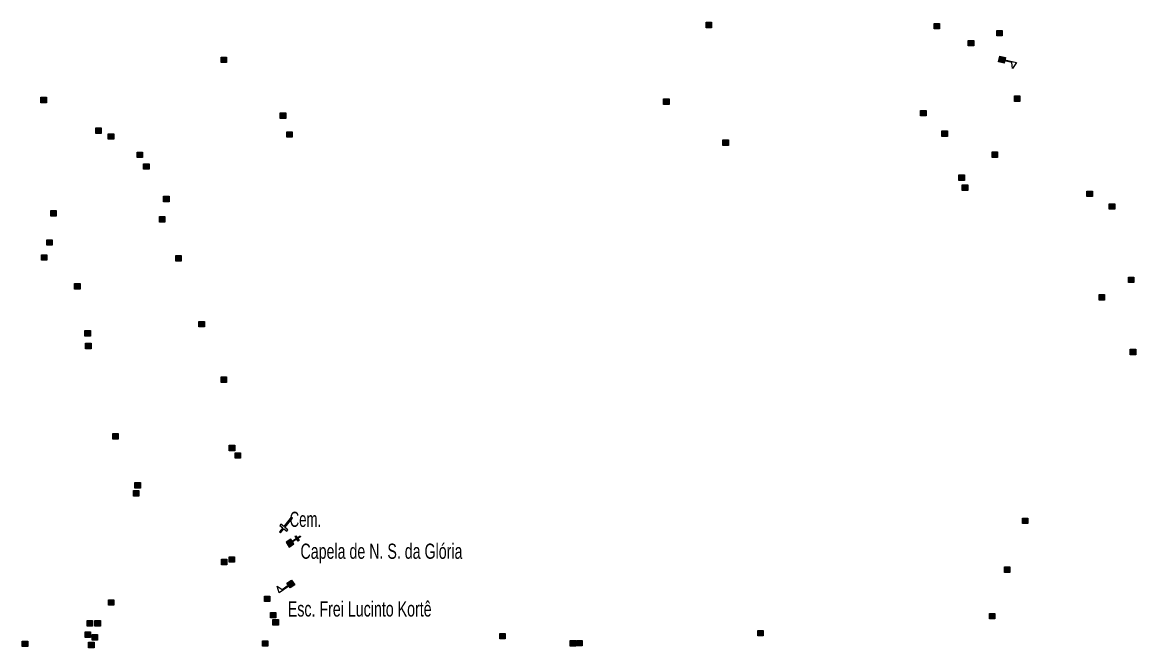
# Model space of a CAD drawing. Extents: x 649.2 to 674.4, y 7040 to 7068.1.
# Drawn here: x 649.46 to 655.33, y 7043.71 to 7047.01 of the extents above; entities that cross this region are included whole.
import ezdxf

# ---------------------------------------------------------------- set-up
doc = ezdxf.new("R2010")
doc.units = 0
doc.header["$LTSCALE"] = 0.032
for name, color, linetype, lineweight in [('2', 7, 'Continuous', 25), ('20', 7, 'Continuous', 25), ('4', 7, 'Continuous', 25), ('6', 7, 'Continuous', 25)]:
    doc.layers.add(name, color=color, linetype=linetype, lineweight=lineweight)
doc.layers.add('61', color=7, linetype='Continuous')

msp = doc.modelspace()

# ---------------------------------------------------------------- hatches: boundary and pattern name
at = {"layer": '2'}
for points in [[(653.064, 7047.0061), (653.093, 7047.0061), (653.093, 7046.9771), (653.064, 7046.9771)], [(654.2654, 7047), (654.2944, 7047), (654.2944, 7046.971), (654.2654, 7046.971)], [(654.5959, 7046.9633), (654.6249, 7046.9633), (654.6249, 7046.9343), (654.5959, 7046.9343)], [(654.4455, 7046.9105), (654.4745, 7046.9105), (654.4745, 7046.8815), (654.4455, 7046.8815)], [(650.5091, 7046.8224), (650.5381, 7046.8224), (650.5381, 7046.7934), (650.5091, 7046.7934)], [(649.5605, 7046.6114), (649.5895, 7046.6114), (649.5895, 7046.5824), (649.5605, 7046.5824)], [(652.8409, 7046.6023), (652.8699, 7046.6023), (652.8699, 7046.5733), (652.8409, 7046.5733)], [(654.6889, 7046.6178), (654.7179, 7046.6178), (654.7179, 7046.5888), (654.6889, 7046.5888)], [(650.821, 7046.5288), (650.85, 7046.5288), (650.85, 7046.4998), (650.821, 7046.4998)], [(654.1948, 7046.5417), (654.2238, 7046.5417), (654.2238, 7046.5127), (654.1948, 7046.5127)], [(649.8492, 7046.4494), (649.8782, 7046.4494), (649.8782, 7046.4204), (649.8492, 7046.4204)], [(649.915, 7046.419), (649.944, 7046.419), (649.944, 7046.39), (649.915, 7046.39)], [(650.8554, 7046.4291), (650.8844, 7046.4291), (650.8844, 7046.4001), (650.8554, 7046.4001)], [(654.3066, 7046.4341), (654.3356, 7046.4341), (654.3356, 7046.4051), (654.3066, 7046.4051)], [(653.1535, 7046.3868), (653.1825, 7046.3868), (653.1825, 7046.3578), (653.1535, 7046.3578)], [(650.0672, 7046.3227), (650.0962, 7046.3227), (650.0962, 7046.2937), (650.0672, 7046.2937)], [(654.5714, 7046.3233), (654.6004, 7046.3233), (654.6004, 7046.2943), (654.5714, 7046.2943)], [(650.1013, 7046.2606), (650.1303, 7046.2606), (650.1303, 7046.2316), (650.1013, 7046.2316)], [(654.3963, 7046.202), (654.4253, 7046.202), (654.4253, 7046.173), (654.3963, 7046.173)], [(654.4142, 7046.1493), (654.4432, 7046.1493), (654.4432, 7046.1203), (654.4142, 7046.1203)], [(655.0705, 7046.1168), (655.0995, 7046.1168), (655.0995, 7046.0878), (655.0705, 7046.0878)], [(650.2061, 7046.0901), (650.2351, 7046.0901), (650.2351, 7046.0611), (650.2061, 7046.0611)], [(649.6117, 7046.0146), (649.6407, 7046.0146), (649.6407, 7045.9856), (649.6117, 7045.9856)], [(655.1885, 7046.05), (655.2175, 7046.05), (655.2175, 7046.021), (655.1885, 7046.021)], [(650.1844, 7045.9826), (650.2134, 7045.9826), (650.2134, 7045.9536), (650.1844, 7045.9536)], [(649.5912, 7045.8607), (649.6202, 7045.8607), (649.6202, 7045.8317), (649.5912, 7045.8317)], [(649.5631, 7045.7817), (649.5921, 7045.7817), (649.5921, 7045.7527), (649.5631, 7045.7527)], [(650.2706, 7045.7776), (650.2996, 7045.7776), (650.2996, 7045.7486), (650.2706, 7045.7486)], [(655.289, 7045.6642), (655.318, 7045.6642), (655.318, 7045.6352), (655.289, 7045.6352)], [(649.7374, 7045.6297), (649.7664, 7045.6297), (649.7664, 7045.6007), (649.7374, 7045.6007)], [(655.1344, 7045.5722), (655.1634, 7045.5722), (655.1634, 7045.5432), (655.1344, 7045.5432)], [(650.3923, 7045.4306), (650.4213, 7045.4306), (650.4213, 7045.4016), (650.3923, 7045.4016)], [(649.7919, 7045.3817), (649.8209, 7045.3817), (649.8209, 7045.3527), (649.7919, 7045.3527)], [(649.7951, 7045.3153), (649.8241, 7045.3153), (649.8241, 7045.2863), (649.7951, 7045.2863)], [(655.2988, 7045.284), (655.3278, 7045.284), (655.3278, 7045.255), (655.2988, 7045.255)], [(650.5094, 7045.1378), (650.5384, 7045.1378), (650.5384, 7045.1088), (650.5094, 7045.1088)], [(649.9387, 7044.8392), (649.9677, 7044.8392), (649.9677, 7044.8102), (649.9387, 7044.8102)], [(650.5526, 7044.778), (650.5816, 7044.778), (650.5816, 7044.749), (650.5526, 7044.749)], [(650.5827, 7044.7388), (650.6117, 7044.7388), (650.6117, 7044.7098), (650.5827, 7044.7098)], [(650.0473, 7044.5396), (650.0763, 7044.5396), (650.0763, 7044.5106), (650.0473, 7044.5106)], [(650.0552, 7044.5816), (650.0842, 7044.5816), (650.0842, 7044.5526), (650.0552, 7044.5526)], [(654.731, 7044.3942), (654.76, 7044.3942), (654.76, 7044.3652), (654.731, 7044.3652)], [(650.5515, 7044.1906), (650.5805, 7044.1906), (650.5805, 7044.1616), (650.5515, 7044.1616)], [(650.5108, 7044.1773), (650.5398, 7044.1773), (650.5398, 7044.1483), (650.5108, 7044.1483)], [(654.6357, 7044.1372), (654.6647, 7044.1372), (654.6647, 7044.1082), (654.6357, 7044.1082)], [(649.9158, 7043.9641), (649.9448, 7043.9641), (649.9448, 7043.9351), (649.9158, 7043.9351)], [(650.7374, 7043.984), (650.7664, 7043.984), (650.7664, 7043.955), (650.7374, 7043.955)], [(650.7692, 7043.8973), (650.7982, 7043.8973), (650.7982, 7043.8683), (650.7692, 7043.8683)], [(654.557, 7043.8925), (654.586, 7043.8925), (654.586, 7043.8635), (654.557, 7043.8635)], [(649.8032, 7043.855), (649.8322, 7043.855), (649.8322, 7043.826), (649.8032, 7043.826)], [(649.8449, 7043.855), (649.8739, 7043.855), (649.8739, 7043.826), (649.8449, 7043.826)], [(650.7827, 7043.8599), (650.8117, 7043.8599), (650.8117, 7043.8309), (650.7827, 7043.8309)], [(649.7925, 7043.7948), (649.8215, 7043.7948), (649.8215, 7043.7658), (649.7925, 7043.7658)], [(649.83, 7043.7805), (649.859, 7043.7805), (649.859, 7043.7515), (649.83, 7043.7515)], [(651.9772, 7043.7873), (652.0062, 7043.7873), (652.0062, 7043.7583), (651.9772, 7043.7583)], [(653.3369, 7043.8026), (653.3659, 7043.8026), (653.3659, 7043.7736), (653.3369, 7043.7736)], [(649.462, 7043.7462), (649.491, 7043.7462), (649.491, 7043.7172), (649.462, 7043.7172)], [(649.8116, 7043.7406), (649.8406, 7043.7406), (649.8406, 7043.7116), (649.8116, 7043.7116)], [(650.7275, 7043.7483), (650.7565, 7043.7483), (650.7565, 7043.7193), (650.7275, 7043.7193)], [(652.3489, 7043.749), (652.3779, 7043.749), (652.3779, 7043.72), (652.3489, 7043.72)], [(652.3825, 7043.7504), (652.4115, 7043.7504), (652.4115, 7043.7214), (652.3825, 7043.7214)]]:
    msp.add_hatch(color=256, dxfattribs=at).paths.add_polyline_path(points)
at = {"layer": '4'}
for points in [[(654.6122, 7046.8274), (654.6414, 7046.8203), (654.6342, 7046.7912), (654.6051, 7046.7983)], [(650.8972, 7044.0436), (650.8727, 7044.0263), (650.8554, 7044.0508), (650.8798, 7044.0681)]]:
    msp.add_hatch(color=256, dxfattribs=at).paths.add_polyline_path(points)
at = {"layer": '6'}
for points in [[(650.8861, 7044.2687), (650.8833, 7044.2729), (650.9063, 7044.288), (650.8995, 7044.2984), (650.9037, 7044.3012), (650.9105, 7044.2907), (650.9252, 7044.3003), (650.9279, 7044.2961), (650.9133, 7044.2865), (650.9201, 7044.2761), (650.9159, 7044.2733), (650.9091, 7044.2838)], [(650.8765, 7044.2834), (650.8514, 7044.267), (650.8678, 7044.2419), (650.8929, 7044.2583)]]:
    msp.add_hatch(color=256, dxfattribs=at).paths.add_polyline_path(points)

# ---------------------------------------------------------------- linework, layer by layer
at = {"layer": '2'}
for points in [[(653.064, 7047.0061), (653.093, 7047.0061), (653.093, 7046.9771), (653.064, 7046.9771)], [(654.2654, 7047), (654.2944, 7047), (654.2944, 7046.971), (654.2654, 7046.971)], [(654.5959, 7046.9633), (654.6249, 7046.9633), (654.6249, 7046.9343), (654.5959, 7046.9343)], [(654.4455, 7046.9105), (654.4745, 7046.9105), (654.4745, 7046.8815), (654.4455, 7046.8815)], [(650.5091, 7046.8224), (650.5381, 7046.8224), (650.5381, 7046.7934), (650.5091, 7046.7934)], [(649.5605, 7046.6114), (649.5895, 7046.6114), (649.5895, 7046.5824), (649.5605, 7046.5824)], [(652.8409, 7046.6023), (652.8699, 7046.6023), (652.8699, 7046.5733), (652.8409, 7046.5733)], [(654.6889, 7046.6178), (654.7179, 7046.6178), (654.7179, 7046.5888), (654.6889, 7046.5888)], [(650.821, 7046.5288), (650.85, 7046.5288), (650.85, 7046.4998), (650.821, 7046.4998)], [(654.1948, 7046.5417), (654.2238, 7046.5417), (654.2238, 7046.5127), (654.1948, 7046.5127)], [(649.8492, 7046.4494), (649.8782, 7046.4494), (649.8782, 7046.4204), (649.8492, 7046.4204)], [(649.915, 7046.419), (649.944, 7046.419), (649.944, 7046.39), (649.915, 7046.39)], [(650.8554, 7046.4291), (650.8844, 7046.4291), (650.8844, 7046.4001), (650.8554, 7046.4001)], [(654.3066, 7046.4341), (654.3356, 7046.4341), (654.3356, 7046.4051), (654.3066, 7046.4051)], [(653.1535, 7046.3868), (653.1825, 7046.3868), (653.1825, 7046.3578), (653.1535, 7046.3578)], [(650.0672, 7046.3227), (650.0962, 7046.3227), (650.0962, 7046.2937), (650.0672, 7046.2937)], [(654.5714, 7046.3233), (654.6004, 7046.3233), (654.6004, 7046.2943), (654.5714, 7046.2943)], [(650.1013, 7046.2606), (650.1303, 7046.2606), (650.1303, 7046.2316), (650.1013, 7046.2316)], [(654.3963, 7046.202), (654.4253, 7046.202), (654.4253, 7046.173), (654.3963, 7046.173)], [(654.4142, 7046.1493), (654.4432, 7046.1493), (654.4432, 7046.1203), (654.4142, 7046.1203)], [(655.0705, 7046.1168), (655.0995, 7046.1168), (655.0995, 7046.0878), (655.0705, 7046.0878)], [(650.2061, 7046.0901), (650.2351, 7046.0901), (650.2351, 7046.0611), (650.2061, 7046.0611)], [(649.6117, 7046.0146), (649.6407, 7046.0146), (649.6407, 7045.9856), (649.6117, 7045.9856)], [(655.1885, 7046.05), (655.2175, 7046.05), (655.2175, 7046.021), (655.1885, 7046.021)], [(650.1844, 7045.9826), (650.2134, 7045.9826), (650.2134, 7045.9536), (650.1844, 7045.9536)], [(649.5912, 7045.8607), (649.6202, 7045.8607), (649.6202, 7045.8317), (649.5912, 7045.8317)], [(649.5631, 7045.7817), (649.5921, 7045.7817), (649.5921, 7045.7527), (649.5631, 7045.7527)], [(650.2706, 7045.7776), (650.2996, 7045.7776), (650.2996, 7045.7486), (650.2706, 7045.7486)], [(655.289, 7045.6642), (655.318, 7045.6642), (655.318, 7045.6352), (655.289, 7045.6352)], [(649.7374, 7045.6297), (649.7664, 7045.6297), (649.7664, 7045.6007), (649.7374, 7045.6007)], [(655.1344, 7045.5722), (655.1634, 7045.5722), (655.1634, 7045.5432), (655.1344, 7045.5432)], [(650.3923, 7045.4306), (650.4213, 7045.4306), (650.4213, 7045.4016), (650.3923, 7045.4016)], [(649.7919, 7045.3817), (649.8209, 7045.3817), (649.8209, 7045.3527), (649.7919, 7045.3527)], [(649.7951, 7045.3153), (649.8241, 7045.3153), (649.8241, 7045.2863), (649.7951, 7045.2863)], [(655.2988, 7045.284), (655.3278, 7045.284), (655.3278, 7045.255), (655.2988, 7045.255)], [(650.5094, 7045.1378), (650.5384, 7045.1378), (650.5384, 7045.1088), (650.5094, 7045.1088)], [(649.9387, 7044.8392), (649.9677, 7044.8392), (649.9677, 7044.8102), (649.9387, 7044.8102)], [(650.5526, 7044.778), (650.5816, 7044.778), (650.5816, 7044.749), (650.5526, 7044.749)], [(650.5827, 7044.7388), (650.6117, 7044.7388), (650.6117, 7044.7098), (650.5827, 7044.7098)], [(650.0473, 7044.5396), (650.0763, 7044.5396), (650.0763, 7044.5106), (650.0473, 7044.5106)], [(650.0552, 7044.5816), (650.0842, 7044.5816), (650.0842, 7044.5526), (650.0552, 7044.5526)], [(654.731, 7044.3942), (654.76, 7044.3942), (654.76, 7044.3652), (654.731, 7044.3652)], [(650.5515, 7044.1906), (650.5805, 7044.1906), (650.5805, 7044.1616), (650.5515, 7044.1616)], [(650.5108, 7044.1773), (650.5398, 7044.1773), (650.5398, 7044.1483), (650.5108, 7044.1483)], [(654.6357, 7044.1372), (654.6647, 7044.1372), (654.6647, 7044.1082), (654.6357, 7044.1082)], [(649.9158, 7043.9641), (649.9448, 7043.9641), (649.9448, 7043.9351), (649.9158, 7043.9351)], [(650.7374, 7043.984), (650.7664, 7043.984), (650.7664, 7043.955), (650.7374, 7043.955)], [(650.7692, 7043.8973), (650.7982, 7043.8973), (650.7982, 7043.8683), (650.7692, 7043.8683)], [(654.557, 7043.8925), (654.586, 7043.8925), (654.586, 7043.8635), (654.557, 7043.8635)], [(649.8032, 7043.855), (649.8322, 7043.855), (649.8322, 7043.826), (649.8032, 7043.826)], [(649.8449, 7043.855), (649.8739, 7043.855), (649.8739, 7043.826), (649.8449, 7043.826)], [(650.7827, 7043.8599), (650.8117, 7043.8599), (650.8117, 7043.8309), (650.7827, 7043.8309)], [(649.7925, 7043.7948), (649.8215, 7043.7948), (649.8215, 7043.7658), (649.7925, 7043.7658)], [(649.83, 7043.7805), (649.859, 7043.7805), (649.859, 7043.7515), (649.83, 7043.7515)], [(651.9772, 7043.7873), (652.0062, 7043.7873), (652.0062, 7043.7583), (651.9772, 7043.7583)], [(653.3369, 7043.8026), (653.3659, 7043.8026), (653.3659, 7043.7736), (653.3369, 7043.7736)], [(649.462, 7043.7462), (649.491, 7043.7462), (649.491, 7043.7172), (649.462, 7043.7172)], [(649.8116, 7043.7406), (649.8406, 7043.7406), (649.8406, 7043.7116), (649.8116, 7043.7116)], [(650.7275, 7043.7483), (650.7565, 7043.7483), (650.7565, 7043.7193), (650.7275, 7043.7193)], [(652.3489, 7043.749), (652.3779, 7043.749), (652.3779, 7043.72), (652.3489, 7043.72)], [(652.3825, 7043.7504), (652.4115, 7043.7504), (652.4115, 7043.7214), (652.3825, 7043.7214)]]:
    msp.add_lwpolyline(points, close=True, dxfattribs=at)
at = {"layer": '20'}
for points in [[(650.8394, 7044.35), (650.8236, 7044.3625), (650.8184, 7044.3559), (650.834, 7044.3434)], [(650.8852, 7044.3948), (650.8789, 7044.3997), (650.8394, 7044.35)], [(650.8403, 7044.3385), (650.8559, 7044.3259), (650.8613, 7044.3326), (650.8455, 7044.3451), (650.8852, 7044.3948)], [(650.834, 7044.3434), (650.8166, 7044.3215), (650.8228, 7044.3166), (650.8403, 7044.3385)]]:
    msp.add_lwpolyline(points, dxfattribs=at)
at = {"layer": '4'}
for p, q in [((654.6384, 7046.8082), (654.6372, 7046.8033)), ((650.8655, 7044.0365), (650.8626, 7044.0406))]:
    msp.add_line(p, q, dxfattribs=at)
for points in [[(654.6122, 7046.8274), (654.6414, 7046.8203), (654.6342, 7046.7912), (654.6051, 7046.7983)], [(654.6384, 7046.8082), (654.6991, 7046.7934), (654.6787, 7046.7623), (654.6756, 7046.794), (654.6372, 7046.8033)], [(650.8972, 7044.0436), (650.8727, 7044.0263), (650.8554, 7044.0508), (650.8798, 7044.0681)], [(650.8655, 7044.0365), (650.8145, 7044.0004), (650.8044, 7044.0362), (650.8303, 7044.0177), (650.8626, 7044.0406)]]:
    msp.add_lwpolyline(points, close=True, dxfattribs=at)
at = {"layer": '6'}
for points in [[(650.8861, 7044.2687), (650.8833, 7044.2729), (650.9063, 7044.288), (650.8995, 7044.2984), (650.9037, 7044.3012), (650.9105, 7044.2907), (650.9252, 7044.3003), (650.9279, 7044.2961), (650.9133, 7044.2865), (650.9201, 7044.2761), (650.9159, 7044.2733), (650.9091, 7044.2838)], [(650.8765, 7044.2834), (650.8514, 7044.267), (650.8678, 7044.2419), (650.8929, 7044.2583)]]:
    msp.add_lwpolyline(points, close=True, dxfattribs=at)

# ---------------------------------------------------------------- texts
at = {"layer": '61'}
for s, width, p in [('Cem.', 0.65, (650.8705, 7044.3481)), ('Capela de N. S. da Glória', 0.7, (650.9276, 7044.18)), ('Esc. Frei Lucinto Kortê', 0.7, (650.861, 7043.8759))]:
    msp.add_text(s, height=0.08, dxfattribs=dict(at, width=width)).set_placement(p)

doc.saveas('drawing.dxf')
